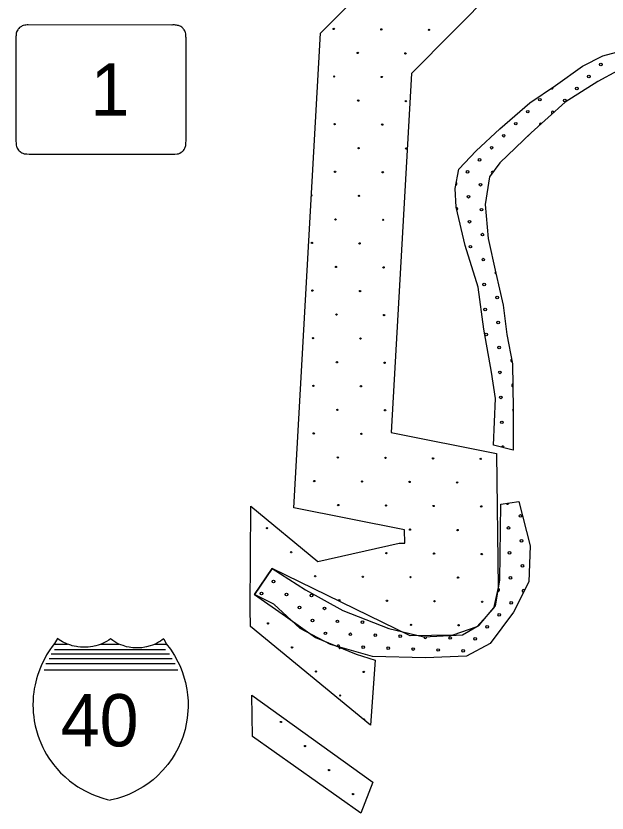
# Model space of a CAD drawing. Extents: x 1612280 to 1883141, y 560852 to 780851.
# Drawn here: x 1658591 to 1663363, y 636801 to 643239 of the extents above; entities that cross this region are included whole.
import ezdxf

# ---------------------------------------------------------------- set-up
doc = ezdxf.new("R2010")
doc.units = 0
for name, color, linetype in [('DESIGN - EROSION CONTROL - Devices', 7, 'Continuous'), ('DESIGN - ROW - Slope Lines', 7, 'Continuous'), ('DESIGN - SCRATCH - User 1', 7, 'Continuous'), ('DESIGN - TRAFFIC CONTROL PERMANENT - Pavement Marking Text', 7, 'Continuous'), ('SURVEY - DRAINAGE - Bridge Hydraulic Data with Text', 7, 'Continuous')]:
    doc.layers.add(name, color=color, linetype=linetype)

msp = doc.modelspace()

# ---------------------------------------------------------------- linework, layer by layer
at = {"layer": 'DESIGN - EROSION CONTROL - Devices'}
for centre in [(1661156.4, 643134), (1661156.4, 643134), (1661540.9, 643130.3), (1661540.9, 643130.3), (1661925.5, 643126.6), (1661925.5, 643126.6), (1661350.5, 642939.9), (1661350.5, 642939.9), (1661735.1, 642936.1), (1661735.1, 642936.1), (1661160.1, 642749.5), (1661160.1, 642749.5), (1661544.7, 642745.7), (1661544.7, 642745.7), (1661354.3, 642555.3), (1661354.3, 642555.3), (1661738.8, 642551.6), (1661738.8, 642551.6), (1661163.9, 642364.9), (1661163.9, 642364.9), (1661548.4, 642361.2), (1661548.4, 642361.2), (1661358, 642170.8), (1661358, 642170.8), (1661742.5, 642167), (1661742.5, 642167), (1661167.6, 641980.4), (1661167.6, 641980.4), (1661552.1, 641976.6), (1661552.1, 641976.6), (1661361.7, 641786.2), (1661361.7, 641786.2), (1661171.3, 641595.8), (1661171.3, 641595.8), (1661555.9, 641592.1), (1661555.9, 641592.1), (1660980.9, 641405.4), (1660980.9, 641405.4), (1661365.5, 641401.7), (1661365.5, 641401.7), (1661175.1, 641211.3), (1661175.1, 641211.3), (1661559.6, 641207.5), (1661559.6, 641207.5), (1660984.6, 641020.8), (1660984.6, 641020.8), (1661369.2, 641017.1), (1661369.2, 641017.1), (1661178.8, 640826.7), (1661178.8, 640826.7), (1661563.3, 640823), (1661563.3, 640823), (1660988.4, 640636.3), (1660988.4, 640636.3), (1661372.9, 640632.6), (1661372.9, 640632.6), (1661182.5, 640442.1), (1661182.5, 640442.1), (1661567.1, 640438.4), (1661567.1, 640438.4), (1660992.1, 640251.7), (1660992.1, 640251.7), (1661376.7, 640248), (1661376.7, 640248), (1661186.3, 640057.6), (1661186.3, 640057.6), (1661570.8, 640053.9), (1661570.8, 640053.9), (1660995.8, 639867.2), (1660995.8, 639867.2), (1661380.4, 639863.5), (1661380.4, 639863.5), (1661190, 639673), (1661190, 639673), (1661574.5, 639669.3), (1661574.5, 639669.3), (1661959.1, 639665.6), (1661959.1, 639665.6), (1662343.6, 639661.8), (1662343.6, 639661.8), (1660999.6, 639482.6), (1660999.6, 639482.6), (1661384.1, 639478.9), (1661384.1, 639478.9), (1661768.7, 639475.2), (1661768.7, 639475.2), (1662153.2, 639471.4), (1662153.2, 639471.4), (1661193.7, 639288.5), (1661193.7, 639288.5), (1661578.3, 639284.8), (1661578.3, 639284.8), (1661962.8, 639281), (1661962.8, 639281), (1662347.4, 639277.3), (1662347.4, 639277.3), (1660618.8, 639101.8), (1660618.8, 639101.8), (1661772.4, 639090.6), (1661772.4, 639090.6), (1662157, 639086.9), (1662157, 639086.9), (1660812.9, 638907.7), (1660812.9, 638907.7), (1661582, 638900.2), (1661582, 638900.2), (1661966.6, 638896.5), (1661966.6, 638896.5), (1662351.1, 638892.7), (1662351.1, 638892.7), (1661007, 638713.5), (1661007, 638713.5), (1661391.6, 638709.8), (1661391.6, 638709.8), (1661776.2, 638706.1), (1661776.2, 638706.1), (1662160.7, 638702.3), (1662160.7, 638702.3), (1661201.2, 638519.4), (1661201.2, 638519.4), (1661585.7, 638515.6), (1661585.7, 638515.6), (1661970.3, 638511.9), (1661970.3, 638511.9), (1662354.8, 638508.2), (1662354.8, 638508.2), (1660626.2, 638332.7), (1660626.2, 638332.7), (1661779.9, 638321.5), (1661779.9, 638321.5), (1662164.4, 638317.8), (1662164.4, 638317.8), (1660820.4, 638138.6), (1660820.4, 638138.6), (1661014.5, 637944.4), (1661014.5, 637944.4), (1661399.1, 637940.7), (1661399.1, 637940.7), (1661208.7, 637750.3), (1661208.7, 637750.3), (1660730.7, 637536.5), (1660730.7, 637536.5), (1660924.9, 637342.3), (1660924.9, 637342.3), (1661119, 637148.2), (1661119, 637148.2), (1661313.2, 636954), (1661313.2, 636954)]:
    msp.add_circle(centre, 5.28, dxfattribs=at)
for centre, start, end in [((1660977.2, 641790), 271.26514, 82.30796), ((1660622.5, 638717.3), 79.2948, 212.81757), ((1661204.9, 638134.8), 99.2739, 36.40447), ((1661402.8, 637556.1), 289.3103, 171.67846)]:
    msp.add_arc(centre, 5.28, start, end, dxfattribs=at)
at = {"layer": 'DESIGN - ROW - Slope Lines'}
msp.add_line((1658591.5, 643064.4), (1658591.5, 642232.7), dxfattribs=at)
msp.add_line((1658591.5, 643064.4), (1658591.5, 642232.7), dxfattribs=at)
for points in [[(1659964.3, 643054), (1659964.2, 643061.8), (1659964.1, 643069.8), (1659963, 643084.4), (1659961.7, 643094.9), (1659959.9, 643105.7), (1659957.9, 643111.7), (1659954.7, 643118.3), (1659950.3, 643125.8), (1659944.9, 643133.2), (1659940.1, 643138.6), (1659934.3, 643144.2), (1659929.6, 643148), (1659923.1, 643152.5), (1659918.2, 643155.4), (1659909.8, 643159.4), (1659903.7, 643161.6), (1659896.5, 643162.9), (1659887.2, 643164.4), (1659879.1, 643165.2), (1659870.5, 643165.7), (1659858.2, 643165.8), (1659848.7, 643165.2), (1658691.4, 643165.9), (1658682, 643165.8), (1658671.8, 643165.2), (1658662.6, 643164), (1658653.5, 643162.4), (1658649.3, 643161), (1658642, 643158), (1658635.6, 643154.6), (1658630.4, 643151.4), (1658621.4, 643144.5), (1658615.4, 643138.7), (1658610.2, 643132.9), (1658606.3, 643127.6), (1658600.6, 643118), (1658597.2, 643110.6), (1658595.2, 643105.5), (1658594.5, 643101.7), (1658594, 643098.3), (1658593.2, 643091.1), (1658592.1, 643081.8), (1658591.6, 643073.9), (1658591.5, 643067.1), (1658591.5, 643049.2)], [(1659964.3, 643054), (1659964.2, 643061.8), (1659964.1, 643069.8), (1659963, 643084.4), (1659961.7, 643094.9), (1659959.9, 643105.7), (1659957.9, 643111.7), (1659954.7, 643118.3), (1659950.3, 643125.8), (1659944.9, 643133.2), (1659940.1, 643138.6), (1659934.3, 643144.2), (1659929.6, 643148), (1659923.1, 643152.5), (1659918.2, 643155.4), (1659909.8, 643159.4), (1659903.7, 643161.6), (1659896.5, 643162.9), (1659887.2, 643164.4), (1659879.1, 643165.2), (1659870.5, 643165.7), (1659858.2, 643165.8), (1659848.7, 643165.2), (1658691.4, 643165.9), (1658682, 643165.8), (1658671.8, 643165.2), (1658662.6, 643164), (1658653.5, 643162.4), (1658649.3, 643161), (1658642, 643158), (1658635.6, 643154.6), (1658630.4, 643151.4), (1658621.4, 643144.5), (1658615.4, 643138.7), (1658610.2, 643132.9), (1658606.3, 643127.6), (1658600.6, 643118), (1658597.2, 643110.6), (1658595.2, 643105.5), (1658594.5, 643101.7), (1658594, 643098.3), (1658593.2, 643091.1), (1658592.1, 643081.8), (1658591.6, 643073.9), (1658591.5, 643067.1), (1658591.5, 643049.2)], [(1659854.5, 642123.3), (1659875.1, 642123.6), (1659892.1, 642123.9), (1659902.4, 642126.3), (1659914.7, 642131.2), (1659925.8, 642137.6), (1659934.7, 642144.4), (1659942.8, 642152.4), (1659949.1, 642160.4), (1659955.1, 642170.2), (1659958.7, 642177.9), (1659961.2, 642185), (1659962.8, 642192.5), (1659963.6, 642200.7), (1659963.9, 642210.8), (1659964.3, 642234.1), (1659964.3, 643054)], [(1659854.5, 642123.3), (1659875.1, 642123.6), (1659892.1, 642123.9), (1659902.4, 642126.3), (1659914.7, 642131.2), (1659925.8, 642137.6), (1659934.7, 642144.4), (1659942.8, 642152.4), (1659949.1, 642160.4), (1659955.1, 642170.2), (1659958.7, 642177.9), (1659961.2, 642185), (1659962.8, 642192.5), (1659963.6, 642200.7), (1659963.9, 642210.8), (1659964.3, 642234.1), (1659964.3, 643054)], [(1658591.5, 642232.7), (1658591.6, 642223.6), (1658592.1, 642213.5), (1658592.9, 642204.1), (1658594, 642194.9), (1658595.4, 642185.6), (1658598.2, 642178), (1658601.6, 642170.8), (1658606.1, 642163.3), (1658611.5, 642156), (1658617.1, 642149.8), (1658624.4, 642143.2), (1658631.4, 642138), (1658639.4, 642133.3), (1658648, 642129.3), (1658656.9, 642126.2), (1658664.1, 642125.3), (1658679.1, 642124), (1658697.9, 642123.3), (1659854.5, 642123.3)], [(1658591.5, 642232.7), (1658591.6, 642223.6), (1658592.1, 642213.5), (1658592.9, 642204.1), (1658594, 642194.9), (1658595.4, 642185.6), (1658598.2, 642178), (1658601.6, 642170.8), (1658606.1, 642163.3), (1658611.5, 642156), (1658617.1, 642149.8), (1658624.4, 642143.2), (1658631.4, 642138), (1658639.4, 642133.3), (1658648, 642129.3), (1658656.9, 642126.2), (1658664.1, 642125.3), (1658679.1, 642124), (1658697.9, 642123.3), (1659854.5, 642123.3)]]:
    msp.add_lwpolyline(points, dxfattribs=at)
at = {"layer": 'DESIGN - SCRATCH - User 1'}
for points in [[(1660487.6, 639279.2), (1661029.3, 638832.6), (1661684.8, 638980.3), (1661729.5, 638981.1), (1661728.3, 639088.7), (1660835.9, 639266.7), (1661051.2, 643100.5), (1665466.1, 647542.7), (1665535.1, 648509.4), (1666303.1, 648398.2)], [(1660487.6, 639279.2), (1661029.3, 638832.6), (1661684.8, 638980.3), (1661729.5, 638981.1), (1661728.3, 639088.7), (1660835.9, 639266.7), (1661051.2, 643100.5), (1665466.1, 647542.7), (1665535.1, 648509.4), (1666303.1, 648398.2)], [(1666303.1, 648398.2), (1666772.4, 648319.9), (1666790.7, 647824.7), (1661784, 642774.5), (1661621.2, 639874.8), (1662471.3, 639705.2), (1662483.6, 638623), (1662446.9, 638451.9), (1662312.5, 638305.1), (1662117, 638237.9), (1661774.9, 638231.7), (1660659.5, 638776), (1660518.3, 638566.2), (1660768.5, 638391.5), (1661009.2, 638219.4), (1661337.8, 638085.6), (1661490.6, 638035.9), (1661454.1, 637510.3), (1660485.5, 638308.9)], [(1666303.1, 648398.2), (1666772.4, 648319.9), (1666790.7, 647824.7), (1661784, 642774.5), (1661621.2, 639874.8), (1662471.3, 639705.2), (1662483.6, 638623), (1662446.9, 638451.9), (1662312.5, 638305.1), (1662117, 638237.9), (1661774.9, 638231.7), (1660659.5, 638776), (1660518.3, 638566.2), (1660768.5, 638391.5), (1661009.2, 638219.4), (1661337.8, 638085.6), (1661490.6, 638035.9), (1661454.1, 637510.3), (1660485.5, 638308.9)], [(1662445.8, 639772), (1662461.3, 640149.4), (1662430.3, 640361.4), (1662368.3, 640707.8), (1662321.8, 641049), (1662218.4, 641385.1), (1662146.1, 641695.3), (1662135.8, 641845.2), (1662166.8, 642000.3), (1662306.3, 642150.3), (1662497.5, 642326.1), (1662740.3, 642538), (1662947, 642677.6), (1663164, 642832.7), (1663329.3, 642915.5), (1663520.5, 642967.2)], [(1662445.8, 639772), (1662461.3, 640149.4), (1662430.3, 640361.4), (1662368.3, 640707.8), (1662321.8, 641049), (1662218.4, 641385.1), (1662146.1, 641695.3), (1662135.8, 641845.2), (1662166.8, 642000.3), (1662306.3, 642150.3), (1662497.5, 642326.1), (1662740.3, 642538), (1662947, 642677.6), (1663164, 642832.7), (1663329.3, 642915.5), (1663520.5, 642967.2)], [(1663448.2, 642796.5), (1663288, 642708.7), (1663024.5, 642543.2), (1662750.6, 642295), (1662497.5, 642052), (1662414.8, 641938.3), (1662378.6, 641716), (1662404.4, 641441.9), (1662466.4, 641162.7), (1662523.3, 640904.2), (1662554.3, 640666.4), (1662600.8, 640428.6), (1662606, 640066.7), (1662606, 639730.6), (1662445.8, 639772)], [(1663448.2, 642796.5), (1663288, 642708.7), (1663024.5, 642543.2), (1662750.6, 642295), (1662497.5, 642052), (1662414.8, 641938.3), (1662378.6, 641716), (1662404.4, 641441.9), (1662466.4, 641162.7), (1662523.3, 640904.2), (1662554.3, 640666.4), (1662600.8, 640428.6), (1662606, 640066.7), (1662606, 639730.6), (1662445.8, 639772)], [(1660485.5, 638308.9), (1660483.1, 638450), (1660487.6, 639279.2)], [(1660485.5, 638308.9), (1660483.1, 638450), (1660487.6, 639279.2)], [(1662505.9, 639294.7), (1662651.5, 639316.1), (1662741.5, 638960.3), (1662732.9, 638668.8), (1662608.7, 638424.5), (1662420.2, 638171.6), (1662227.4, 638068.7), (1661897.5, 638055.8), (1661469.2, 638064.4), (1661130.7, 638163), (1660886.6, 638291.6), (1660672.4, 638488.8), (1660518.1, 638565.9), (1660659.5, 638776)], [(1662505.9, 639294.7), (1662651.5, 639316.1), (1662741.5, 638960.3), (1662732.9, 638668.8), (1662608.7, 638424.5), (1662420.2, 638171.6), (1662227.4, 638068.7), (1661897.5, 638055.8), (1661469.2, 638064.4), (1661130.7, 638163), (1660886.6, 638291.6), (1660672.4, 638488.8), (1660518.1, 638565.9), (1660659.5, 638776)], [(1660659.5, 638776), (1660929.4, 638604.5), (1661229.3, 638437.3), (1661602, 638291.6), (1661884.7, 638223), (1662197.4, 638240.2), (1662330.2, 638317.3), (1662463, 638475.9), (1662497.3, 638681.7), (1662505.9, 639294.7)], [(1660659.5, 638776), (1660929.4, 638604.5), (1661229.3, 638437.3), (1661602, 638291.6), (1661884.7, 638223), (1662197.4, 638240.2), (1662330.2, 638317.3), (1662463, 638475.9), (1662497.3, 638681.7), (1662505.9, 639294.7)], [(1660500.6, 637418.1), (1660494.9, 637752.1)], [(1660494.9, 637752.1), (1661472.5, 637051.7)], [(1660500.6, 637418.1), (1660494.9, 637752.1)], [(1660494.9, 637752.1), (1661472.5, 637051.7)], [(1661472.5, 637051.7), (1661374.7, 636801.1), (1660500.6, 637418.1)], [(1661472.5, 637051.7), (1661374.7, 636801.1), (1660500.6, 637418.1)]]:
    msp.add_lwpolyline(points, dxfattribs=at)
at = {"layer": 'DESIGN - TRAFFIC CONTROL PERMANENT - Pavement Marking Text'}
for centre in [(1663312.6, 642846.5), (1663312.6, 642846.5), (1663215.5, 642749.4), (1663215.5, 642749.4), (1663118.5, 642652.3), (1663118.5, 642652.3), (1662819.8, 642562.7), (1662819.8, 642562.7), (1663021.4, 642555.2), (1663021.4, 642555.2), (1662722.7, 642465.6), (1662722.7, 642465.6), (1662625.7, 642368.6), (1662625.7, 642368.6), (1662528.6, 642271.5), (1662528.6, 642271.5), (1662431.5, 642174.4), (1662431.5, 642174.4), (1662334.4, 642077.3), (1662334.4, 642077.3), (1662237.4, 641980.3), (1662237.4, 641980.3), (1662341.9, 641875.7), (1662341.9, 641875.7), (1662244.8, 641778.7), (1662244.8, 641778.7), (1662349.4, 641674.1), (1662349.4, 641674.1), (1662252.3, 641577.1), (1662252.3, 641577.1), (1662356.8, 641472.5), (1662356.8, 641472.5), (1662259.8, 641375.4), (1662259.8, 641375.4), (1662364.3, 641270.9), (1662364.3, 641270.9), (1662371.8, 641069.3), (1662371.8, 641069.3), (1662476.3, 640964.8), (1662476.3, 640964.8), (1662379.2, 640867.7), (1662379.2, 640867.7), (1662483.8, 640763.1), (1662483.8, 640763.1), (1662386.7, 640666.1), (1662386.7, 640666.1), (1662491.2, 640561.5), (1662491.2, 640561.5), (1662498.7, 640359.9), (1662498.7, 640359.9), (1662506.2, 640158.3), (1662506.2, 640158.3), (1662513.6, 639956.7), (1662513.6, 639956.7), (1662664.8, 639200.7), (1662664.8, 639200.7), (1662567.7, 639103.6), (1662567.7, 639103.6), (1662672.3, 638999.1), (1662672.3, 638999.1), (1662575.2, 638902), (1662575.2, 638902), (1662679.7, 638797.5), (1662679.7, 638797.5), (1662582.7, 638700.4), (1662582.7, 638700.4), (1660671.1, 638670.6), (1660671.1, 638670.6), (1660574, 638573.5), (1660574, 638573.5), (1660775.6, 638566), (1660775.6, 638566), (1660977.3, 638558.6), (1660977.3, 638558.6), (1662590.1, 638498.8), (1662590.1, 638498.8), (1660880.2, 638461.5), (1660880.2, 638461.5), (1661081.8, 638454), (1661081.8, 638454), (1660984.7, 638356.9), (1660984.7, 638356.9), (1662493.1, 638401.7), (1662493.1, 638401.7), (1661186.3, 638349.5), (1661186.3, 638349.5), (1661387.9, 638342), (1661387.9, 638342), (1662396, 638304.7), (1662396, 638304.7), (1661089.3, 638252.4), (1661089.3, 638252.4), (1661290.9, 638244.9), (1661290.9, 638244.9), (1661492.5, 638237.5), (1661492.5, 638237.5), (1661694.1, 638230), (1661694.1, 638230), (1662097.3, 638215.1), (1662097.3, 638215.1), (1662298.9, 638207.6), (1662298.9, 638207.6), (1661395.4, 638140.4), (1661395.4, 638140.4), (1661597, 638132.9), (1661597, 638132.9), (1661798.6, 638125.5), (1661798.6, 638125.5), (1662000.2, 638118), (1662000.2, 638118), (1662201.8, 638110.5), (1662201.8, 638110.5)]:
    msp.add_circle(centre, 10.6, dxfattribs=at)
for centre, start, end in [((1662916.9, 642659.8), 225.2579, 22.81651), ((1662924.3, 642458.2), 18.53395, 245.8333), ((1662827.3, 642361.1), 55.92942, 208.43783), ((1662730.2, 642264), 94.93956, 172.71205), ((1662439, 641972.8), 50.04507, 237.93308), ((1662140.3, 641883.2), 275.24855, 62.14707), ((1662147.8, 641681.6), 291.26724, 94.98233), ((1662468.8, 641166.4), 119.73604, 265.22056), ((1662595.8, 640457), 104.03238, 278.09264), ((1662603.3, 640255.4), 90.76814, 270.87028), ((1662610.7, 640053.8), 116.78613, 243.21353), ((1662521.1, 639755.1), 331.77368, 179.27065), ((1662560.3, 639305.3), 202.36246, 354.38122), ((1662485.6, 638603.4), 253.34867, 87.73671), ((1662687.2, 638595.9), 16.3253, 289.77432), ((1660678.6, 638469), 37.03043, 57.70421), ((1661895.7, 638222.5), 177.28735, 8.99096), ((1661193.8, 638147.9), 326.64781, 180.86796)]:
    msp.add_arc(centre, 10.6, start, end, dxfattribs=at)
at = {"layer": 'SURVEY - DRAINAGE - Bridge Hydraulic Data with Text'}
for p, q in [((1658900, 638164.5), (1659006.6, 638164.5)), ((1658900, 638164.5), (1659006.6, 638164.5)), ((1658903.9, 638121.3), (1659798.1, 638121.3)), ((1658903.9, 638121.3), (1659798.1, 638121.3)), ((1659275.8, 638164.5), (1659423.1, 638164.5)), ((1659275.8, 638164.5), (1659423.1, 638164.5)), ((1659708.6, 638164.5), (1659808.4, 638164.5)), ((1659708.6, 638164.5), (1659808.4, 638164.5)), ((1658859.2, 638048.4), (1659851.3, 638048.4)), ((1658859.2, 638048.4), (1659851.3, 638048.4)), ((1658876.3, 638087.4), (1659832.1, 638087.4)), ((1658876.3, 638087.4), (1659832.1, 638087.4)), ((1658831.6, 638008.1), (1659876.8, 638008.1)), ((1658831.6, 638008.1), (1659876.8, 638008.1)), ((1658819.9, 637957.4), (1659897.1, 637957.4)), ((1658819.9, 637957.4), (1659897.1, 637957.4))]:
    msp.add_line(p, q, dxfattribs=at)
for points in [[(1658926.7, 638209.7), (1658904, 638170.8), (1658885, 638146.4), (1658865.5, 638119.1), (1658855, 638103.3), (1658839.4, 638078.2), (1658823.6, 638050.4), (1658805.6, 638015), (1658794.8, 637991.4), (1658783, 637963.1), (1658765.2, 637912.6), (1658757.1, 637885.2), (1658750.8, 637861.2), (1658745.4, 637837), (1658739.2, 637804), (1658735.2, 637776.7), (1658731.7, 637744.9), (1658729.5, 637711.9), (1658728.7, 637672.6), (1658729.3, 637643.9), (1658731.1, 637613.6), (1658734.9, 637577), (1658739.4, 637546.1), (1658747.1, 637506.3), (1658756.6, 637467.8), (1658768.1, 637429.5), (1658778.3, 637400.5), (1658791.5, 637367.4), (1658808.4, 637330.6), (1658821.9, 637304.2), (1658838.3, 637275), (1658857.9, 637243.7), (1658893.7, 637193.6), (1658920.4, 637160.9), (1658951.4, 637127.2), (1658987.5, 637092.3), (1659024.9, 637060.5), (1659092.2, 637012.4), (1659143.9, 636982.2), (1659203, 636953.6), (1659239, 636939.1), (1659292.3, 636921.2), (1659329.1, 636911.4), (1659351.9, 636905.7)], [(1658926.7, 638209.7), (1658904, 638170.8), (1658885, 638146.4), (1658865.5, 638119.1), (1658855, 638103.3), (1658839.4, 638078.2), (1658823.6, 638050.4), (1658805.6, 638015), (1658794.8, 637991.4), (1658783, 637963.1), (1658765.2, 637912.6), (1658757.1, 637885.2), (1658750.8, 637861.2), (1658745.4, 637837), (1658739.2, 637804), (1658735.2, 637776.7), (1658731.7, 637744.9), (1658729.5, 637711.9), (1658728.7, 637672.6), (1658729.3, 637643.9), (1658731.1, 637613.6), (1658734.9, 637577), (1658739.4, 637546.1), (1658747.1, 637506.3), (1658756.6, 637467.8), (1658768.1, 637429.5), (1658778.3, 637400.5), (1658791.5, 637367.4), (1658808.4, 637330.6), (1658821.9, 637304.2), (1658838.3, 637275), (1658857.9, 637243.7), (1658893.7, 637193.6), (1658920.4, 637160.9), (1658951.4, 637127.2), (1658987.5, 637092.3), (1659024.9, 637060.5), (1659092.2, 637012.4), (1659143.9, 636982.2), (1659203, 636953.6), (1659239, 636939.1), (1659292.3, 636921.2), (1659329.1, 636911.4), (1659351.9, 636905.7)], [(1659785, 638208.4), (1659772.6, 638199.1), (1659758, 638189.3), (1659743, 638180.3), (1659727.1, 638171.7), (1659714.7, 638165.7), (1659692.9, 638156.7), (1659675, 638150.5), (1659646.2, 638142.8), (1659631.1, 638139.7), (1659606.6, 638136.2), (1659593.9, 638135.1), (1659577.8, 638134.3), (1659557.5, 638134.5), (1659549, 638134.9), (1659535, 638136), (1659518, 638138.1), (1659504.9, 638140.3), (1659484.2, 638144.8), (1659456.5, 638153), (1659438.5, 638159.7), (1659423.1, 638166.3), (1659398.9, 638178.6), (1659374.7, 638193.5), (1659355.8, 638207.1), (1659341, 638197.2), (1659321.4, 638185.6), (1659301, 638175.2), (1659285.4, 638168.3), (1659271, 638162.6), (1659254.8, 638157), (1659235.6, 638151.5), (1659223.5, 638148.6), (1659213, 638146.4), (1659194, 638143.2), (1659174.5, 638141.1), (1659160.6, 638140.1), (1659146.7, 638139.8), (1659128.5, 638140), (1659111.4, 638141.1), (1659092.2, 638143.2), (1659079.2, 638145.3), (1659060.1, 638149.2), (1659045, 638152.9), (1659033.4, 638156.4), (1659018.3, 638161.4), (1659006.7, 638165.8), (1658995.7, 638170.4), (1658978.4, 638178.4), (1658966.2, 638184.8), (1658955, 638191.1), (1658939.8, 638200.6), (1658926.7, 638209.7)], [(1659785, 638208.4), (1659772.6, 638199.1), (1659758, 638189.3), (1659743, 638180.3), (1659727.1, 638171.7), (1659714.7, 638165.7), (1659692.9, 638156.7), (1659675, 638150.5), (1659646.2, 638142.8), (1659631.1, 638139.7), (1659606.6, 638136.2), (1659593.9, 638135.1), (1659577.8, 638134.3), (1659557.5, 638134.5), (1659549, 638134.9), (1659535, 638136), (1659518, 638138.1), (1659504.9, 638140.3), (1659484.2, 638144.8), (1659456.5, 638153), (1659438.5, 638159.7), (1659423.1, 638166.3), (1659398.9, 638178.6), (1659374.7, 638193.5), (1659355.8, 638207.1), (1659341, 638197.2), (1659321.4, 638185.6), (1659301, 638175.2), (1659285.4, 638168.3), (1659271, 638162.6), (1659254.8, 638157), (1659235.6, 638151.5), (1659223.5, 638148.6), (1659213, 638146.4), (1659194, 638143.2), (1659174.5, 638141.1), (1659160.6, 638140.1), (1659146.7, 638139.8), (1659128.5, 638140), (1659111.4, 638141.1), (1659092.2, 638143.2), (1659079.2, 638145.3), (1659060.1, 638149.2), (1659045, 638152.9), (1659033.4, 638156.4), (1659018.3, 638161.4), (1659006.7, 638165.8), (1658995.7, 638170.4), (1658978.4, 638178.4), (1658966.2, 638184.8), (1658955, 638191.1), (1658939.8, 638200.6), (1658926.7, 638209.7)], [(1659785, 638208.4), (1659804.8, 638167.6), (1659837.9, 638124.1), (1659870.1, 638074.8), (1659898.8, 638022.5), (1659915.8, 637986.2), (1659936.1, 637935.2), (1659950.4, 637890.8), (1659959.7, 637856), (1659971.1, 637799.7), (1659977.2, 637755.2), (1659980.7, 637707.5), (1659981.3, 637655.5), (1659974.6, 637568.6), (1659966.7, 637520.7), (1659956.2, 637475.2), (1659937.5, 637413.9), (1659922.5, 637374.4), (1659897.3, 637319.5), (1659876.8, 637281.6), (1659852.5, 637242.3), (1659816.8, 637192.5), (1659778.5, 637146.9), (1659732.1, 637099.9), (1659698.1, 637070.2), (1659655.2, 637037.1), (1659618.5, 637012.3), (1659545.9, 636971.5), (1659503.6, 636952.2), (1659459.6, 636935.2), (1659411, 636919.8), (1659351.9, 636905.7)], [(1659785, 638208.4), (1659804.8, 638167.6), (1659837.9, 638124.1), (1659870.1, 638074.8), (1659898.8, 638022.5), (1659915.8, 637986.2), (1659936.1, 637935.2), (1659950.4, 637890.8), (1659959.7, 637856), (1659971.1, 637799.7), (1659977.2, 637755.2), (1659980.7, 637707.5), (1659981.3, 637655.5), (1659974.6, 637568.6), (1659966.7, 637520.7), (1659956.2, 637475.2), (1659937.5, 637413.9), (1659922.5, 637374.4), (1659897.3, 637319.5), (1659876.8, 637281.6), (1659852.5, 637242.3), (1659816.8, 637192.5), (1659778.5, 637146.9), (1659732.1, 637099.9), (1659698.1, 637070.2), (1659655.2, 637037.1), (1659618.5, 637012.3), (1659545.9, 636971.5), (1659503.6, 636952.2), (1659459.6, 636935.2), (1659411, 636919.8), (1659351.9, 636905.7)]]:
    msp.add_lwpolyline(points, dxfattribs=at)

# ---------------------------------------------------------------- texts
at = {"layer": 'DESIGN - ROW - Slope Lines'}
msp.add_text('1', height=422.4, rotation=0.00108, dxfattribs=at).set_placement((1659192.8, 642432.5))
msp.add_text('1', height=422.4, rotation=0.00108, dxfattribs=at).set_placement((1659192.8, 642432.5))
at = {"layer": 'SURVEY - DRAINAGE - Bridge Hydraulic Data with Text'}
msp.add_text('40', height=422.4, rotation=0.00129, dxfattribs=at).set_placement((1658952.9, 637339.3))
msp.add_text('40', height=422.4, rotation=0.00129, dxfattribs=at).set_placement((1658952.9, 637339.3))

doc.saveas('drawing.dxf')
